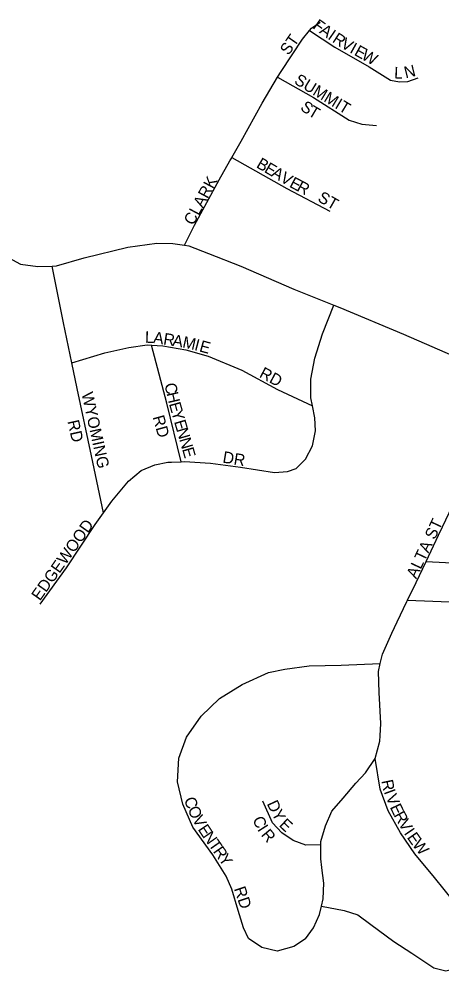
# Model space of a CAD drawing. Extents: x -84548 to 2262448, y -162180 to 525962.
# Drawn here: x 62992 to 64811, y 159998 to 164090 of the extents above; entities that cross this region are included whole.
import ezdxf

# ---------------------------------------------------------------- set-up
doc = ezdxf.new("R2010")
doc.units = 0
for name, color, linetype in [('GM_X_Major_Lake_Text', 7, 'Continuous'), ('GM_X_US_Location', 7, 'Continuous'), ('GM_X_US_Route', 7, 'Continuous')]:
    doc.layers.add(name, color=color, linetype=linetype)

msp = doc.modelspace()

# ---------------------------------------------------------------- linework, layer by layer
at = {"layer": 'GM_X_Major_Lake_Text'}
msp.add_lwpolyline([(62929.8, 163073.5), (62998.2, 163035.9), (63072.3, 163026.5), (63134.5, 163028.5), (63152.4, 163029.1), (63272.2, 163064.1), (63460, 163109.6), (63583.9, 163126.5), (63654, 163125.1), (63704.1, 163118.1), (63722.1, 163115.6), (63806.5, 163082.2), (63945, 163027.2), (64174, 162928.8), (64345.6, 162860.2), (64370.7, 162850.2), (64645.8, 162736.1), (64888.9, 162629.8), (65113.8, 162537.4), (65156.2, 162610.5)], dxfattribs=at)
at = {"layer": 'GM_X_US_Location'}
for points in [[(63907.1, 163493.9), (63907.7, 163495), (63947.6, 163564.9), (64038, 163728.1), (64103.9, 163840), (64118.7, 163865.2), (64211.3, 164004.3), (64240.5, 164040.4), (64248.9, 164050.8), (64286.6, 164077.2)], [(64240.5, 164040.4), (64349.8, 163969.6), (64496.8, 163884.9), (64589.5, 163827.7), (64627.6, 163820), (64663.6, 163822.4), (64707.5, 163836.8)], [(64103.9, 163840), (64258, 163752.3), (64411.1, 163655.6), (64465.3, 163638.1), (64529.4, 163632.7)], [(63704.1, 163118.1), (63747.1, 163204.2), (63853.2, 163399.6), (63899.1, 163480), (63907.1, 163493.9)], [(63907.7, 163495), (64143.9, 163362.4), (64329, 163264)], [(63355.3, 161967.5), (63303, 162211.9), (63241.9, 162501.8), (63218.9, 162611.9), (63183, 162783.8), (63134.5, 163028.5)], [(63646.5, 162185.6), (63647, 162185.6), (63689.6, 162187.2), (63703.6, 162187.7), (63815.7, 162180.8), (63944, 162164), (64090.4, 162141.4), (64146.4, 162145.9), (64184.3, 162158.3), (64223.9, 162198.8), (64253.4, 162255.2), (64266.7, 162319.5), (64264.1, 162375.6), (64254, 162427.3), (64247.2, 162461.6), (64246.4, 162541.7), (64263.5, 162632.1), (64296.4, 162736.6), (64345.6, 162860.2)], [(63218.9, 162611.9), (63360.4, 162655.3), (63464.3, 162678.4), (63542.3, 162689.2), (63562.1, 162688.2), (63610.3, 162685.8), (63708.6, 162668.7), (63805, 162641.6), (63949.7, 162580.9), (64102.7, 162498.2), (64254, 162427.3)], [(63689.6, 162187.2), (63626.9, 162439.5), (63562.1, 162688.2)], [(64659.7, 161585.9), (64659.8, 161586.1), (64662.6, 161591.9), (64699.8, 161668.4), (64742.2, 161758.2), (64795.8, 161871.7), (64812.6, 161907.3), (64899.6, 162091.2), (64956.1, 162208.2), (65015.3, 162330.8), (65027.3, 162356.1)], [(63083.3, 161574.4), (63195.8, 161731.8), (63320, 161917.4), (63355.3, 161967.5), (63391, 162018.3), (63462.2, 162103.2), (63517.8, 162149.8), (63575.6, 162174.4), (63631.5, 162185), (63646.5, 162185.6)], [(64742.2, 161758.2), (64937.2, 161748.9), (65181.5, 161735.2), (65439.9, 161721.7), (65690.3, 161706.1), (65692.7, 161664), (65737.1, 161636.4), (65773.5, 161600.7), (65799.9, 161601), (65800, 161601)], [(64662.6, 161591.9), (64880.8, 161584), (65103.1, 161576.1), (65321.4, 161566.2), (65501.6, 161562), (65613.7, 161563.1), (65643.5, 161581.4), (65673.2, 161621.8), (65692.7, 161664)], [(64595.2, 161449.8), (64595.3, 161449.9), (64617.5, 161499.2), (64659.7, 161585.9)], [(64544.3, 161009), (64544.3, 161009.3), (64547.9, 161061.7), (64540.5, 161195.9), (64537.6, 161286), (64545.5, 161320.1), (64554.9, 161360.3), (64595.2, 161449.8)], [(64223.2, 160136.6), (64173.5, 160104.1), (64101.7, 160083.3), (64035.4, 160098.7), (63979, 160138.2), (63956.5, 160184.1), (63933.7, 160258.1), (63906.7, 160350), (63882.1, 160405.8), (63825.1, 160497.5), (63739.8, 160616.9), (63696.8, 160714.7), (63673.8, 160810.6), (63678.7, 160912.9), (63711.8, 161003.4), (63774.9, 161094.2), (63854.2, 161169.1), (63951.7, 161230.2), (64065.2, 161281.4), (64135.1, 161296.1), (64239.1, 161309.2), (64377.2, 161312.5), (64545.5, 161320.1)], [(64294.3, 160443.3), (64289.7, 160480), (64289.1, 160540.1), (64289, 160554.1), (64310.3, 160622.5), (64337.6, 160684.9), (64385.1, 160741.4), (64440.5, 160806.1), (64482.1, 160850.6), (64523.5, 160911.1), (64542.7, 160985.5), (64544.3, 161009)], [(64292.4, 160276.9), (64390.1, 160258.5), (64448.4, 160239), (64504.8, 160197.5), (64603.7, 160124.3), (64680.3, 160075), (64775, 160011.8), (64827.2, 159998.2), (64869.1, 160008.7), (64910.7, 160053.2), (64942.2, 160107.6), (64939.5, 160165.7), (64919, 160215.6), (64862.1, 160297.2), (64779, 160400.6), (64693.9, 160502), (64632.9, 160591.5), (64579.8, 160687.2), (64544.9, 160779.1), (64523.5, 160911.1)], [(64289.1, 160540.1), (64225, 160539.5), (64170.8, 160559), (64122.4, 160592.6), (64081.9, 160634.3), (64040.9, 160728)], [(64223.2, 160136.6), (64258.8, 160183.1), (64284.2, 160241.4), (64292.4, 160276.9), (64299.5, 160307.7), (64302.8, 160375.9), (64294.5, 160441.6), (64294.3, 160443.3)]]:
    msp.add_lwpolyline(points, dxfattribs=at)

# ---------------------------------------------------------------- texts
at = {"layer": 'GM_X_US_Route'}
for s, rotation, p in [('F', 325.0483, (64251.4, 164052.4)), ('A', 325.0366, (64280.2, 164032.2)), ('ST', 55.2978, (64151, 163931.4)), ('I', 325.0343, (64316.3, 164007)), ('R', 326.748, (64335.7, 163993.5)), ('V', 330.3936, (64371.8, 163969.9)), ('I', 330.9397, (64410.5, 163947.9)), ('E', 330.9497, (64429.7, 163937.3)), ('W', 330.9514, (64460.5, 163920.2)), ('L', 357.3763, (64604.1, 163835.1)), ('N', 13.712, (64654.4, 163835)), ('SUMMIT', 328.8601, (64171.6, 163815.2)), ('S', 322.234, (64197.8, 163703.9)), ('T', 329.365, (64231.2, 163678.6)), ('B', 329.4236, (64008.7, 163454.4)), ('E', 329.4552, (64042.9, 163434.2)), ('A', 329.4242, (64073.2, 163416.3)), ('V', 329.4467, (64111.1, 163393.9)), ('CLARK', 61.7824, (63741.3, 163200.2)), ('E', 331.7811, (64150.9, 163370.5)), ('R', 332.166, (64182.2, 163353.7)), ('ST', 330.2509, (64272.6, 163309.3)), ('L', 358.0326, (63533, 162698.8)), ('A', 352.3924, (63566.9, 162697.7)), ('R', 350.9169, (63610.1, 162692)), ('A', 350.9278, (63649.3, 162685.7)), ('M', 347.7043, (63692, 162678.9)), ('I', 345.2642, (63743, 162667.8)), ('E', 344.7377, (63764.2, 162662.2)), ('RD', 332.0983, (64021.5, 162552.6)), ('C', 282.8581, (63616.8, 162520.3)), ('WYOMING', 282.4389, (63260.4, 162480.7)), ('H', 283.1058, (63625.7, 162481.4)), ('E', 285.6442, (63636.3, 162436.2)), ('Y', 286.1913, (63645.9, 162401.9)), ('RD', 285.5276, (63566.1, 162379.4)), ('RD', 282.534, (63200, 162361.2)), ('E', 286.2185, (63658.2, 162359.6)), ('N', 286.2156, (63668, 162325.8)), ('N', 286.2156, (63680.3, 162283.5)), ('E', 286.2185, (63692.6, 162241.3)), ('DR', 350.5357, (63864.9, 162183.9)), ('EDGEWOOD', 54.7126, (63081.9, 161586.3)), ('ALTA ST', 64.7456, (64700.1, 161681.3)), ('R', 281.1933, (64549.9, 160815.8)), ('I', 290.0272, (64559.8, 160769)), ('C', 288.5617, (63700.9, 160736.6)), ('D', 294.908, (64056.4, 160717.8)), ('V', 291.4337, (64567.8, 160747.1)), ('O', 294.8479, (63715.7, 160693.5)), ('Y', 297.7305, (64076.1, 160675.6)), ('E', 295.4422, (64585.4, 160702.7)), ('V', 297.9583, (63735.5, 160650.9)), ('C', 293.5063, (63994.9, 160650.4)), ('E', 316.6827, (64107.2, 160622.5)), ('R', 298.4421, (64601.8, 160668.4)), ('V', 299.6367, (64621.2, 160632.6)), ('E', 303.8632, (63759, 160607.2)), ('I', 302.4857, (64014.7, 160606.6)), ('R', 309.432, (64030.4, 160582.7)), ('I', 304.2478, (64645.2, 160590.7)), ('N', 304.9081, (63779.2, 160577.1)), ('E', 305.0882, (64658.1, 160571.9)), ('W', 308.5162, (64680.3, 160540.5)), ('T', 304.9087, (63804.4, 160541)), ('R', 304.9025, (63824.5, 160512.2)), ('Y', 304.8912, (63847.2, 160479.7)), ('RD', 288.4368, (63915.8, 160352))]:
    msp.add_text(s, height=50, rotation=rotation, dxfattribs=at).set_placement(p)

doc.saveas('drawing.dxf')
